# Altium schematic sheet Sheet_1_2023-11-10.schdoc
size 292 x 163 mm
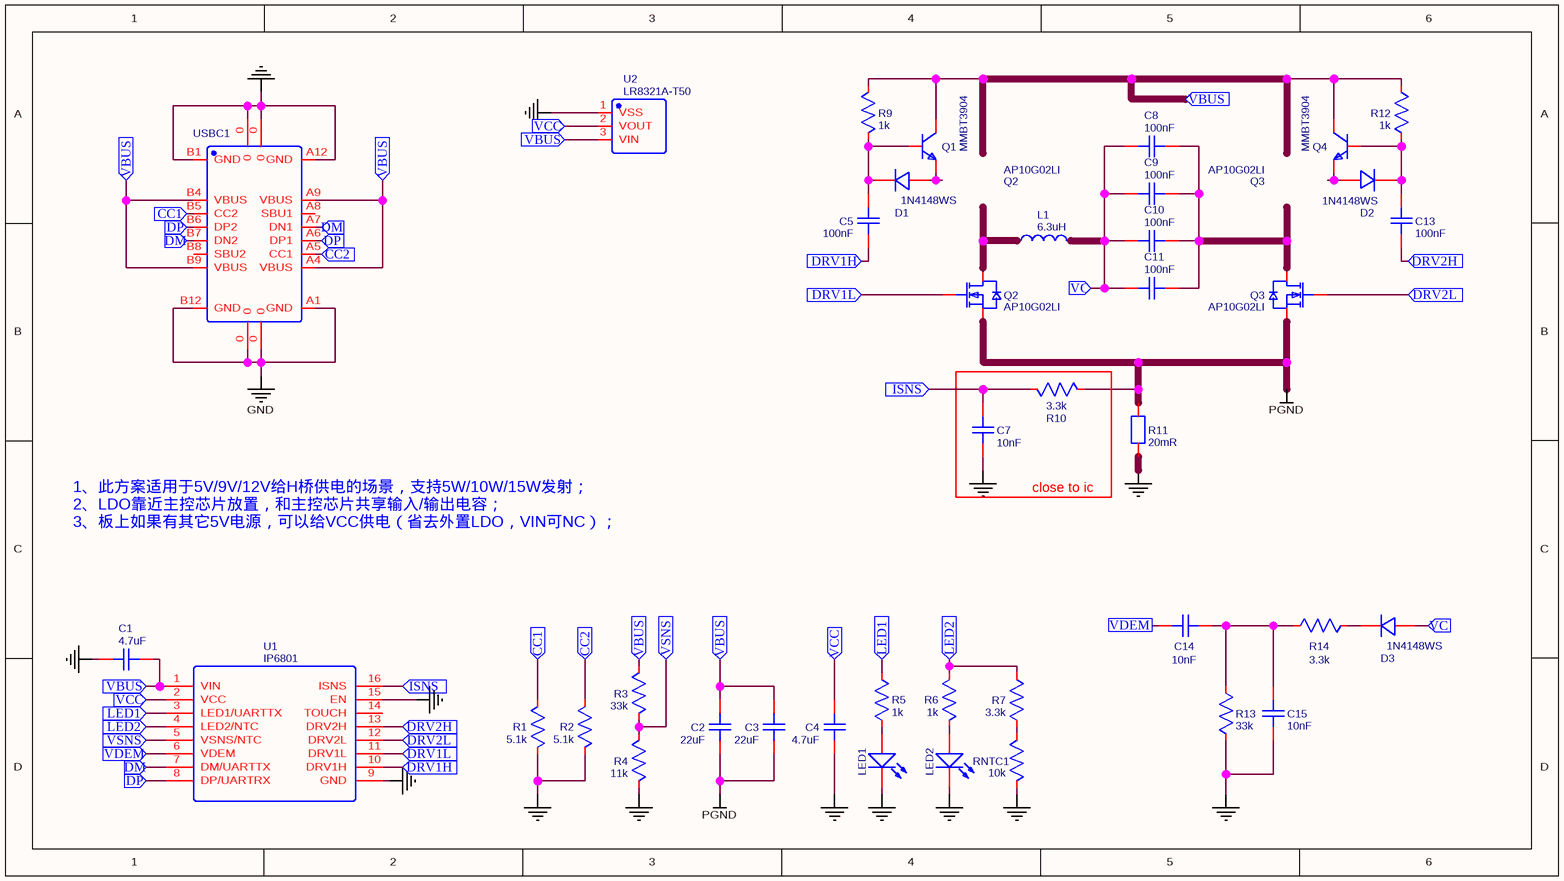
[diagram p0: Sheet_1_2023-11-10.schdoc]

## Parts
(Parts that share a designator on the sheet are numbered #1, #2 ... from top to bottom, then left to right.)
C1  4.7uF  [C0603]
C2  22uF  [C0805]
C3  22uF  [C0805]
C4  4.7uF  [C0603]
C5  100nF  [C0603]
C7  10nF  [C0603]
C8  100nF  [C1206]
C9  100nF  [C1206]
C10  100nF  [C1206]
C11  100nF  [C1206]
C13  100nF  [C0603]
C14  10nF  [C0603]
C15  10nF  [C0603]
D1  1N4148WS  [SOD-323_L1.8-W1.3-LS2.5-RD]
D2  1N4148WS  [SOD-323_L1.8-W1.3-LS2.5-RD]
D3  1N4148WS  [SOD-323_L1.8-W1.3-LS2.5-RD]
L1  6.3uH  [IND-SMD_L4.5-W3.0]
LED1  LED  [LED0603_GREEN]  (value not drawn)
LED2  LED  [LED0603_RED]  (value not drawn)
Q1  MMBT3904  [SOT-23-3_L2.9-W1.3-P0.95-LS2.4-BR]
Q2#1  AP10G02LI  [SOT-23-6_L2.9-W1.6-P0.95-LS2.7-BL]
Q2#2  AP10G02LI  [SOT-23-6_L2.9-W1.6-P0.95-LS2.7-BL]
Q3#1  AP10G02LI  [SOT-23-6_L2.9-W1.6-P0.95-LS2.7-BL]
Q3#2  AP10G02LI  [SOT-23-6_L2.9-W1.6-P0.95-LS2.7-BL]
Q4  MMBT3904  [SOT-23-3_L2.9-W1.3-P0.95-LS2.4-BR]
R1  5.1k  [R0603]
R2  5.1k  [R0603]
R3  33k  [R0603]
R4  11k  [R0603]
R5  1k  [R0603]
R6  1k  [R0603]
R7  3.3k  [R0603]
R9  1k  [R0603]
R10  3.3k  [R0603]
R11  20mR  [R1206]
R12  1k  [R0603]
R13  33k  [R0603]
R14  3.3k  [R0603]
RNTC1  10k  [R0603]
U1  IP6801  [SOP16L]
U2  LR8321A-T50  [SOT-23-3_L2.9-W1.6-P1.90-LS2.8-BR]
USBC1  TYPE-C-31-M-12  [USB-C_SMD-TYPE-C-31-M-12]  (value not drawn)

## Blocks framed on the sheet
close to ic: C7 R10

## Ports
CC1 (in), CC2 (in), DM (in), DP (in), DRV1H (in), DRV1L (in), DRV2H (in), DRV2L (in), ISNS (in), LED1 (in), LED2 (in), VBUS (in), VC (in), VCC (in), VDEM (in), VSNS (in)

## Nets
GND: C1.2 C4.1 C7.1 C15.1 LED1.2(K) LED2.2(K) R1.1 R2.1 R4.1 R11.2 R13.1 RNTC1.1 U1.9(GND) U1.15(EN) U2.1(VSS) USBC1.0 USBC1.A1(GND) USBC1.A12(GND) USBC1.B1(GND) USBC1.B12(GND)
PGND: C2.1 C3.1 Q2#2.5(S) Q3#2.5(S) R10.1 R11.1
CC1: R1.2 USBC1.B5(CC2) ; port CC1
CC2: R2.2 USBC1.A5(CC1) ; port CC2
DM: U1.7(DM/UARTTX) USBC1.A7(DN1) USBC1.B7(DN2) ; port DM
DP: U1.8(DP/UARTRX) USBC1.A6(DP1) USBC1.B6(DP2) ; port DP
DRV1H: C5.1 U1.10(DRV1H) ; port DRV1H
DRV1L: Q2#2.1(G) U1.11(DRV1L) ; port DRV1L
DRV2H: C13.1 U1.13(DRV2H) ; port DRV2H
DRV2L: Q3#2.1(G) U1.12(DRV2L) ; port DRV2L
ISNS: C7.2 R10.2 U1.16(ISNS) ; port ISNS
LED1: R5.2 U1.3(LED1/UARTTX) ; port LED1
LED2: R6.2 R7.1 U1.4(LED2/NTC) ; port LED2
VBUS: C1.1 C2.2 C3.2 Q1.3(C) Q4.3(C) R3.2 R9.1 R12.1 U1.1(VIN) U2.3(VIN) USBC1.A4(VBUS) USBC1.A9(VBUS) USBC1.B4(VBUS) USBC1.B9(VBUS) ; port VBUS
VC: C8.1 C9.1 C10.1 C11.1 D3.2(A) L1.2 ; port VC
VCC: C4.2 U1.2(VCC) U2.2(VOUT) ; port VCC
VDEM: U1.6(VDEM) ; port VDEM
VSNS: R3.1 R4.2 U1.5(VSNS/NTC) ; port VSNS
NetC5_2: C5.2 D1.1(C) Q1.1(B) R9.2
NetC8_2: C8.2 C9.2 C10.2 C11.2 Q3#2.6(D)
NetC13_2: C13.2 D2.1(C) Q4.1(B) R12.2
NetC14_2: C14.2 C15.2 R13.2 R14.1
NetD1_2: D1.2(A) Q1.2(E)
NetD2_2: D2.2(A) Q4.2(E)
NetD3_1: D3.1(C) R14.2
NetL1_1: L1.1 Q2#2.6(D)
NetLED1_1: LED1.1(A) R5.1
NetLED2_1: LED2.1(A) R6.1
NetR7_2: R7.2 RNTC1.2

Not connected (* = marked no-connect by the designer): C14 1; U1 14(TOUCH); USBC1 A8(SBU1) B8(SBU2)

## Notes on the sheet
- 1、此方案适用于5V/9V/12V给H桥供电的场景，支持5W/10W/15W发射；
  2、LDO靠近主控芯片放置，和主控芯片共享输入/输出电容；
  3、板上如果有其它5V电源，可以给VCC供电（省去外置LDO，VIN可NC）；

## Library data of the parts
C1 C4 = 4.7uF: nameAlias: Value(F); Contributor: LCEDA_Lib
C2 C3 = 22uF: nameAlias: Value(F); Contributor: LCEDA_Lib
C5 C13 = 100nF: nameAlias: Value(F); Contributor: LCEDA_Lib
C7 C14 C15 = 10nF: nameAlias: Value(F); Contributor: LCEDA_Lib
C8-C11 = 100nF: Manufacturer: YAGEO; Manufacturer Part: CC1206KRX7R9BB104; nameAlias: Capacitance
D1-D3 = 1N4148WS: Manufacturer: Hottech(合科泰); Contributor: LCSC
L1 = 6.3uH: Manufacturer: Sunlord; Manufacturer Part: MPH252012S4R7MT; nameAlias: Inductance
LED1 LED2 = LED: Contributor: tycc
Q1 Q4 = MMBT3904: Manufacturer: KUU(永裕泰); Contributor: lcsc
Q2#1 Q2#2 Q3#1 Q3#2 = AP10G02LI: Manufacturer Part: AP8G02LI
R1 R2 = 5.1k: nameAlias: Value(Ω); Contributor: LCEDA_Lib
R3 R13 = 33k: nameAlias: Value(Ω); Contributor: LCEDA_Lib
R4 = 11k: nameAlias: Value(Ω); Contributor: LCEDA_Lib
R5 R6 R9 R12 = 1k: nameAlias: Value(Ω); Contributor: LCEDA_Lib
R7 R10 R14 = 3.3k: nameAlias: Value(Ω); Contributor: LCEDA_Lib
R11 = 20mR: nameAlias: Value(Ω); Contributor: LCEDA_Lib; Package Display: No
RNTC1 = 10k: nameAlias: Value(Ω); Contributor: LCEDA_Lib
U1 = IP6801: Contributor: it173
U2 = LR8321A-T50: Manufacturer: LR(朗瑞); Contributor: lcsc
USBC1 = TYPE-C-31-M-12: Manufacturer: Rectangular Connectors - Contacts; Contributor: LCSC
